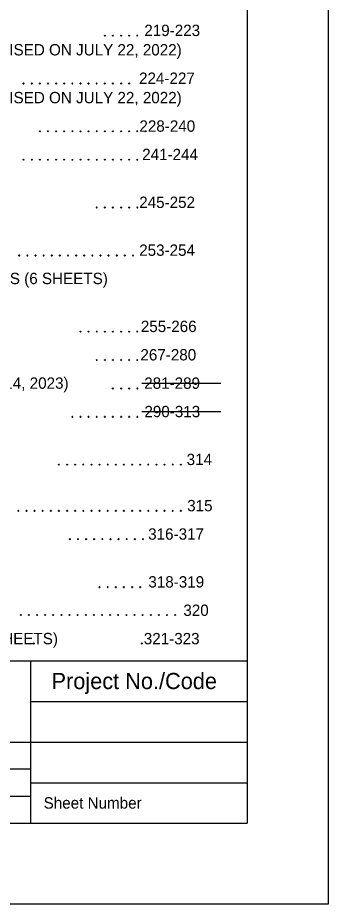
# Model space of a CAD drawing. Extents: x 0 to 1.42, y 0 to 0.92.
# Drawn here: x 1.2574 to 1.4167, y 0 to 0.4557 of the extents above; entities that cross this region are included whole.
import ezdxf

# ---------------------------------------------------------------- set-up
doc = ezdxf.new("R2010")
doc.units = 0
for name, color, linetype in [('DRAFT_Text-Notes', 7, 'Continuous'), ('DRAFT_Text-Titles', 7, 'Continuous'), ('SHEET_Lines', 7, 'Continuous'), ('SHEET_Plot Boundary', 7, 'Continuous'), ('SHEET_Text-Border Info', 7, 'Continuous'), ('SHEET_Text-Titles', 7, 'Continuous')]:
    doc.layers.add(name, color=color, linetype=linetype)

msp = doc.modelspace()

# ---------------------------------------------------------------- linework, layer by layer
at = {"layer": 'DRAFT_Text-Notes'}
for centre in [(1.30206, 0.44647), (1.30622, 0.44647), (1.31039, 0.44647), (1.31456, 0.44647), (1.31872, 0.44647), (1.26039, 0.42188), (1.26456, 0.42188), (1.26872, 0.42188), (1.27289, 0.42188), (1.27706, 0.42188), (1.28122, 0.42188), (1.28539, 0.42188), (1.28956, 0.42188), (1.29372, 0.42188), (1.29789, 0.42188), (1.30206, 0.42188), (1.30622, 0.42188), (1.31039, 0.42188), (1.31456, 0.42188), (1.26872, 0.39729), (1.27289, 0.39729), (1.27706, 0.39729), (1.28122, 0.39729), (1.28539, 0.39729), (1.28956, 0.39729), (1.29372, 0.39729), (1.29789, 0.39729), (1.30206, 0.39729), (1.30622, 0.39729), (1.31039, 0.39729), (1.31456, 0.39729), (1.31872, 0.39729), (1.32289, 0.39729), (1.26039, 0.3827), (1.26456, 0.3827), (1.26872, 0.3827), (1.27289, 0.3827), (1.27706, 0.3827), (1.28122, 0.3827), (1.28539, 0.3827), (1.28956, 0.3827), (1.29372, 0.3827), (1.29789, 0.3827), (1.30206, 0.3827), (1.30622, 0.3827), (1.31039, 0.3827), (1.31456, 0.3827), (1.31872, 0.3827), (1.29789, 0.3581), (1.30206, 0.3581), (1.30622, 0.3581), (1.31039, 0.3581), (1.31456, 0.3581), (1.31872, 0.3581), (1.25816, 0.33351), (1.26232, 0.33351), (1.26649, 0.33351), (1.27066, 0.33351), (1.27482, 0.33351), (1.27899, 0.33351), (1.28316, 0.33351), (1.28732, 0.33351), (1.29149, 0.33351), (1.29566, 0.33351), (1.29982, 0.33351), (1.30399, 0.33351), (1.30816, 0.33351), (1.31232, 0.33351), (1.31649, 0.33351), (1.28956, 0.29433), (1.29372, 0.29433), (1.29789, 0.29433), (1.30206, 0.29433), (1.30622, 0.29433), (1.31039, 0.29433), (1.31456, 0.29433), (1.31872, 0.29433), (1.29789, 0.27974), (1.30206, 0.27974), (1.30622, 0.27974), (1.31039, 0.27974), (1.31456, 0.27974), (1.31872, 0.27974), (1.30622, 0.26514), (1.31039, 0.26514), (1.31456, 0.26514), (1.31872, 0.26514), (1.28539, 0.25055), (1.28956, 0.25055), (1.29372, 0.25055), (1.29789, 0.25055), (1.30206, 0.25055), (1.30622, 0.25055), (1.31039, 0.25055), (1.31456, 0.25055), (1.31872, 0.25055), (1.27852, 0.22596), (1.28269, 0.22596), (1.28686, 0.22596), (1.29102, 0.22596), (1.29519, 0.22596), (1.29936, 0.22596), (1.30352, 0.22596), (1.30769, 0.22596), (1.31186, 0.22596), (1.31602, 0.22596), (1.32019, 0.22596), (1.32436, 0.22596), (1.32852, 0.22596), (1.33269, 0.22596), (1.33686, 0.22596), (1.34102, 0.22596), (1.25769, 0.2022), (1.26186, 0.2022), (1.26602, 0.2022), (1.27019, 0.2022), (1.27436, 0.2022), (1.27852, 0.2022), (1.28269, 0.2022), (1.28686, 0.2022), (1.29102, 0.2022), (1.29519, 0.2022), (1.29936, 0.2022), (1.30352, 0.2022), (1.30769, 0.2022), (1.31186, 0.2022), (1.31602, 0.2022), (1.32019, 0.2022), (1.32436, 0.2022), (1.32852, 0.2022), (1.33269, 0.2022), (1.33686, 0.2022), (1.34102, 0.2022), (1.28412, 0.1876), (1.28828, 0.1876), (1.29245, 0.1876), (1.29662, 0.1876), (1.30078, 0.1876), (1.30495, 0.1876), (1.30912, 0.1876), (1.31328, 0.1876), (1.31745, 0.1876), (1.32162, 0.1876), (1.29936, 0.16301), (1.30352, 0.16301), (1.30769, 0.16301), (1.31186, 0.16301), (1.31602, 0.16301), (1.32019, 0.16301), (1.25895, 0.14866), (1.26311, 0.14866), (1.26728, 0.14866), (1.27145, 0.14866), (1.27561, 0.14866), (1.27978, 0.14866), (1.28395, 0.14866), (1.28811, 0.14866), (1.29228, 0.14866), (1.29645, 0.14866), (1.30061, 0.14866), (1.30478, 0.14866), (1.30895, 0.14866), (1.31311, 0.14866), (1.31728, 0.14866), (1.32145, 0.14866), (1.32561, 0.14866), (1.32978, 0.14866), (1.33395, 0.14866), (1.33811, 0.14866), (1.26568, 0.13407), (1.321, 0.13407)]:
    msp.add_circle(centre, 0.000208, dxfattribs=at)
for centre, start, end in [((1.30206, 0.44647), 0, 180), ((1.30622, 0.44647), 0, 180), ((1.31039, 0.44647), 0, 180), ((1.31456, 0.44647), 0, 180), ((1.31872, 0.44647), 0, 180), ((1.30206, 0.44647), 180, 0), ((1.30622, 0.44647), 180, 0), ((1.31039, 0.44647), 180, 0), ((1.31456, 0.44647), 180, 0), ((1.31872, 0.44647), 180, 0), ((1.26039, 0.42188), 0, 180), ((1.26039, 0.42188), 180, 0), ((1.26456, 0.42188), 0, 180), ((1.26456, 0.42188), 180, 0), ((1.26872, 0.42188), 0, 180), ((1.26872, 0.42188), 180, 0), ((1.27289, 0.42188), 0, 180), ((1.27289, 0.42188), 180, 0), ((1.27706, 0.42188), 0, 180), ((1.27706, 0.42188), 180, 0), ((1.28122, 0.42188), 0, 180), ((1.28122, 0.42188), 180, 0), ((1.28539, 0.42188), 0, 180), ((1.28539, 0.42188), 180, 0), ((1.28956, 0.42188), 0, 180), ((1.28956, 0.42188), 180, 0), ((1.29372, 0.42188), 0, 180), ((1.29372, 0.42188), 180, 0), ((1.29789, 0.42188), 0, 180), ((1.29789, 0.42188), 180, 0), ((1.30206, 0.42188), 0, 180), ((1.30206, 0.42188), 180, 0), ((1.30622, 0.42188), 0, 180), ((1.30622, 0.42188), 180, 0), ((1.31039, 0.42188), 0, 180), ((1.31039, 0.42188), 180, 0), ((1.31456, 0.42188), 0, 180), ((1.31456, 0.42188), 180, 0), ((1.26872, 0.39729), 0, 180), ((1.26872, 0.39729), 180, 0), ((1.27289, 0.39729), 0, 180), ((1.27289, 0.39729), 180, 0), ((1.27706, 0.39729), 0, 180), ((1.27706, 0.39729), 180, 0), ((1.28122, 0.39729), 0, 180), ((1.28122, 0.39729), 180, 0), ((1.28539, 0.39729), 0, 180), ((1.28539, 0.39729), 180, 0), ((1.28956, 0.39729), 0, 180), ((1.28956, 0.39729), 180, 0), ((1.29372, 0.39729), 0, 180), ((1.29372, 0.39729), 180, 0), ((1.29789, 0.39729), 0, 180), ((1.29789, 0.39729), 180, 0), ((1.30206, 0.39729), 0, 180), ((1.30206, 0.39729), 180, 0), ((1.30622, 0.39729), 0, 180), ((1.30622, 0.39729), 180, 0), ((1.31039, 0.39729), 0, 180), ((1.31039, 0.39729), 180, 0), ((1.31456, 0.39729), 0, 180), ((1.31456, 0.39729), 180, 0), ((1.31872, 0.39729), 0, 180), ((1.31872, 0.39729), 180, 0), ((1.32289, 0.39729), 0, 180), ((1.32289, 0.39729), 180, 0), ((1.26039, 0.3827), 0, 180), ((1.26456, 0.3827), 0, 180), ((1.26872, 0.3827), 0, 180), ((1.27289, 0.3827), 0, 180), ((1.27706, 0.3827), 0, 180), ((1.28122, 0.3827), 0, 180), ((1.28539, 0.3827), 0, 180), ((1.28956, 0.3827), 0, 180), ((1.29372, 0.3827), 0, 180), ((1.29789, 0.3827), 0, 180), ((1.30206, 0.3827), 0, 180), ((1.30622, 0.3827), 0, 180), ((1.31039, 0.3827), 0, 180), ((1.31456, 0.3827), 0, 180), ((1.31872, 0.3827), 0, 180), ((1.26039, 0.3827), 180, 0), ((1.26456, 0.3827), 180, 0), ((1.26872, 0.3827), 180, 0), ((1.27289, 0.3827), 180, 0), ((1.27706, 0.3827), 180, 0), ((1.28122, 0.3827), 180, 0), ((1.28539, 0.3827), 180, 0), ((1.28956, 0.3827), 180, 0), ((1.29372, 0.3827), 180, 0), ((1.29789, 0.3827), 180, 0), ((1.30206, 0.3827), 180, 0), ((1.30622, 0.3827), 180, 0), ((1.31039, 0.3827), 180, 0), ((1.31456, 0.3827), 180, 0), ((1.31872, 0.3827), 180, 0), ((1.29789, 0.3581), 0, 180), ((1.29789, 0.3581), 180, 0), ((1.30206, 0.3581), 0, 180), ((1.30206, 0.3581), 180, 0), ((1.30622, 0.3581), 0, 180), ((1.30622, 0.3581), 180, 0), ((1.31039, 0.3581), 0, 180), ((1.31039, 0.3581), 180, 0), ((1.31456, 0.3581), 0, 180), ((1.31456, 0.3581), 180, 0), ((1.31872, 0.3581), 0, 180), ((1.31872, 0.3581), 180, 0), ((1.25816, 0.33351), 0, 180), ((1.25816, 0.33351), 180, 0), ((1.26232, 0.33351), 0, 180), ((1.26232, 0.33351), 180, 0), ((1.26649, 0.33351), 0, 180), ((1.26649, 0.33351), 180, 0), ((1.27066, 0.33351), 0, 180), ((1.27066, 0.33351), 180, 0), ((1.27482, 0.33351), 0, 180), ((1.27482, 0.33351), 180, 0), ((1.27899, 0.33351), 0, 180), ((1.27899, 0.33351), 180, 0), ((1.28316, 0.33351), 0, 180), ((1.28316, 0.33351), 180, 0), ((1.28732, 0.33351), 0, 180), ((1.28732, 0.33351), 180, 0), ((1.29149, 0.33351), 0, 180), ((1.29149, 0.33351), 180, 0), ((1.29566, 0.33351), 0, 180), ((1.29566, 0.33351), 180, 0), ((1.29982, 0.33351), 0, 180), ((1.29982, 0.33351), 180, 0), ((1.30399, 0.33351), 0, 180), ((1.30399, 0.33351), 180, 0), ((1.30816, 0.33351), 0, 180), ((1.30816, 0.33351), 180, 0), ((1.31232, 0.33351), 0, 180), ((1.31232, 0.33351), 180, 0), ((1.31649, 0.33351), 0, 180), ((1.31649, 0.33351), 180, 0), ((1.28956, 0.29433), 0, 180), ((1.28956, 0.29433), 180, 0), ((1.29372, 0.29433), 0, 180), ((1.29372, 0.29433), 180, 0), ((1.29789, 0.29433), 0, 180), ((1.29789, 0.29433), 180, 0), ((1.30206, 0.29433), 0, 180), ((1.30206, 0.29433), 180, 0), ((1.30622, 0.29433), 0, 180), ((1.30622, 0.29433), 180, 0), ((1.31039, 0.29433), 0, 180), ((1.31039, 0.29433), 180, 0), ((1.31456, 0.29433), 0, 180), ((1.31456, 0.29433), 180, 0), ((1.31872, 0.29433), 0, 180), ((1.31872, 0.29433), 180, 0), ((1.29789, 0.27974), 0, 180), ((1.29789, 0.27974), 180, 0), ((1.30206, 0.27974), 0, 180), ((1.30206, 0.27974), 180, 0), ((1.30622, 0.27974), 0, 180), ((1.30622, 0.27974), 180, 0), ((1.31039, 0.27974), 0, 180), ((1.31039, 0.27974), 180, 0), ((1.31456, 0.27974), 0, 180), ((1.31456, 0.27974), 180, 0), ((1.31872, 0.27974), 0, 180), ((1.31872, 0.27974), 180, 0), ((1.30622, 0.26514), 0, 180), ((1.30622, 0.26514), 180, 0), ((1.31039, 0.26514), 0, 180), ((1.31039, 0.26514), 180, 0), ((1.31456, 0.26514), 0, 180), ((1.31456, 0.26514), 180, 0), ((1.31872, 0.26514), 0, 180), ((1.31872, 0.26514), 180, 0), ((1.28539, 0.25055), 0, 180), ((1.28956, 0.25055), 0, 180), ((1.29372, 0.25055), 0, 180), ((1.29789, 0.25055), 0, 180), ((1.30206, 0.25055), 0, 180), ((1.30622, 0.25055), 0, 180), ((1.31039, 0.25055), 0, 180), ((1.31456, 0.25055), 0, 180), ((1.31872, 0.25055), 0, 180), ((1.28539, 0.25055), 180, 0), ((1.28956, 0.25055), 180, 0), ((1.29372, 0.25055), 180, 0), ((1.29789, 0.25055), 180, 0), ((1.30206, 0.25055), 180, 0), ((1.30622, 0.25055), 180, 0), ((1.31039, 0.25055), 180, 0), ((1.31456, 0.25055), 180, 0), ((1.31872, 0.25055), 180, 0), ((1.27852, 0.22596), 0, 180), ((1.27852, 0.22596), 180, 0), ((1.28269, 0.22596), 0, 180), ((1.28269, 0.22596), 180, 0), ((1.28686, 0.22596), 0, 180), ((1.28686, 0.22596), 180, 0), ((1.29102, 0.22596), 0, 180), ((1.29102, 0.22596), 180, 0), ((1.29519, 0.22596), 0, 180), ((1.29519, 0.22596), 180, 0), ((1.29936, 0.22596), 0, 180), ((1.29936, 0.22596), 180, 0), ((1.30352, 0.22596), 0, 180), ((1.30352, 0.22596), 180, 0), ((1.30769, 0.22596), 0, 180), ((1.30769, 0.22596), 180, 0), ((1.31186, 0.22596), 0, 180), ((1.31186, 0.22596), 180, 0), ((1.31602, 0.22596), 0, 180), ((1.31602, 0.22596), 180, 0), ((1.32019, 0.22596), 0, 180), ((1.32019, 0.22596), 180, 0), ((1.32436, 0.22596), 0, 180), ((1.32436, 0.22596), 180, 0), ((1.32852, 0.22596), 0, 180), ((1.32852, 0.22596), 180, 0), ((1.33269, 0.22596), 0, 180), ((1.33269, 0.22596), 180, 0), ((1.33686, 0.22596), 0, 180), ((1.33686, 0.22596), 180, 0), ((1.34102, 0.22596), 0, 180), ((1.34102, 0.22596), 180, 0), ((1.25769, 0.2022), 0, 180), ((1.25769, 0.2022), 180, 0), ((1.26186, 0.2022), 0, 180), ((1.26186, 0.2022), 180, 0), ((1.26602, 0.2022), 0, 180), ((1.26602, 0.2022), 180, 0), ((1.27019, 0.2022), 0, 180), ((1.27019, 0.2022), 180, 0), ((1.27436, 0.2022), 0, 180), ((1.27436, 0.2022), 180, 0), ((1.27852, 0.2022), 0, 180), ((1.27852, 0.2022), 180, 0), ((1.28269, 0.2022), 0, 180), ((1.28269, 0.2022), 180, 0), ((1.28686, 0.2022), 0, 180), ((1.28686, 0.2022), 180, 0), ((1.29102, 0.2022), 0, 180), ((1.29102, 0.2022), 180, 0), ((1.29519, 0.2022), 0, 180), ((1.29519, 0.2022), 180, 0), ((1.29936, 0.2022), 0, 180), ((1.29936, 0.2022), 180, 0), ((1.30352, 0.2022), 0, 180), ((1.30352, 0.2022), 180, 0), ((1.30769, 0.2022), 0, 180), ((1.30769, 0.2022), 180, 0), ((1.31186, 0.2022), 0, 180), ((1.31186, 0.2022), 180, 0), ((1.31602, 0.2022), 0, 180), ((1.31602, 0.2022), 180, 0), ((1.32019, 0.2022), 0, 180), ((1.32019, 0.2022), 180, 0), ((1.32436, 0.2022), 0, 180), ((1.32436, 0.2022), 180, 0), ((1.32852, 0.2022), 0, 180), ((1.32852, 0.2022), 180, 0), ((1.33269, 0.2022), 0, 180), ((1.33269, 0.2022), 180, 0), ((1.33686, 0.2022), 0, 180), ((1.33686, 0.2022), 180, 0), ((1.34102, 0.2022), 0, 180), ((1.34102, 0.2022), 180, 0), ((1.28412, 0.1876), 0, 180), ((1.28412, 0.1876), 180, 0), ((1.28828, 0.1876), 0, 180), ((1.28828, 0.1876), 180, 0), ((1.29245, 0.1876), 0, 180), ((1.29245, 0.1876), 180, 0), ((1.29662, 0.1876), 0, 180), ((1.29662, 0.1876), 180, 0), ((1.30078, 0.1876), 0, 180), ((1.30078, 0.1876), 180, 0), ((1.30495, 0.1876), 0, 180), ((1.30495, 0.1876), 180, 0), ((1.30912, 0.1876), 0, 180), ((1.30912, 0.1876), 180, 0), ((1.31328, 0.1876), 0, 180), ((1.31328, 0.1876), 180, 0), ((1.31745, 0.1876), 0, 180), ((1.31745, 0.1876), 180, 0), ((1.32162, 0.1876), 0, 180), ((1.32162, 0.1876), 180, 0), ((1.29936, 0.16301), 0, 180), ((1.29936, 0.16301), 180, 0), ((1.30352, 0.16301), 0, 180), ((1.30352, 0.16301), 180, 0), ((1.30769, 0.16301), 0, 180), ((1.30769, 0.16301), 180, 0), ((1.31186, 0.16301), 0, 180), ((1.31186, 0.16301), 180, 0), ((1.31602, 0.16301), 0, 180), ((1.31602, 0.16301), 180, 0), ((1.32019, 0.16301), 0, 180), ((1.32019, 0.16301), 180, 0), ((1.25895, 0.14866), 0, 180), ((1.25895, 0.14866), 180, 0), ((1.26311, 0.14866), 0, 180), ((1.26311, 0.14866), 180, 0), ((1.26728, 0.14866), 0, 180), ((1.26728, 0.14866), 180, 0), ((1.27145, 0.14866), 0, 180), ((1.27145, 0.14866), 180, 0), ((1.27561, 0.14866), 0, 180), ((1.27561, 0.14866), 180, 0), ((1.27978, 0.14866), 0, 180), ((1.27978, 0.14866), 180, 0), ((1.28395, 0.14866), 0, 180), ((1.28395, 0.14866), 180, 0), ((1.28811, 0.14866), 0, 180), ((1.28811, 0.14866), 180, 0), ((1.29228, 0.14866), 0, 180), ((1.29228, 0.14866), 180, 0), ((1.29645, 0.14866), 0, 180), ((1.29645, 0.14866), 180, 0), ((1.30061, 0.14866), 0, 180), ((1.30061, 0.14866), 180, 0), ((1.30478, 0.14866), 0, 180), ((1.30478, 0.14866), 180, 0), ((1.30895, 0.14866), 0, 180), ((1.30895, 0.14866), 180, 0), ((1.31311, 0.14866), 0, 180), ((1.31311, 0.14866), 180, 0), ((1.31728, 0.14866), 0, 180), ((1.31728, 0.14866), 180, 0), ((1.32145, 0.14866), 0, 180), ((1.32145, 0.14866), 180, 0), ((1.32561, 0.14866), 0, 180), ((1.32561, 0.14866), 180, 0), ((1.32978, 0.14866), 0, 180), ((1.32978, 0.14866), 180, 0), ((1.33395, 0.14866), 0, 180), ((1.33395, 0.14866), 180, 0), ((1.33811, 0.14866), 0, 180), ((1.33811, 0.14866), 180, 0), ((1.26568, 0.13407), 0, 180), ((1.26568, 0.13407), 180, 0), ((1.321, 0.13407), 0, 180), ((1.321, 0.13407), 180, 0)]:
    msp.add_arc(centre, 0.000208, start, end, dxfattribs=at)
at = {"layer": 'DRAFT_Text-Titles'}
for p, q in [((1.32109, 0.26781), (1.36153, 0.26781)), ((1.32109, 0.25321), (1.36153, 0.25321))]:
    msp.add_line(p, q, dxfattribs=at)
at = {"layer": 'SHEET_Lines'}
for p, q in [((1.26389, 0.125), (1.26389, 0.04167)), ((1.375, 0.125), (1.375, 0.04167)), ((1.26389, 0.10417), (1.375, 0.10417)), ((0.90278, 0.08333), (1.375, 0.08333)), ((1.26389, 0.06944), (1.18056, 0.06944)), ((1.26389, 0.0625), (1.375, 0.0625)), ((1.01389, 0.05556), (1.26389, 0.05556)), ((0.08333, 0.04167), (1.375, 0.04167))]:
    msp.add_line(p, q, dxfattribs=at)
msp.add_lwpolyline([(0.08333, 0.875), (1.375, 0.875), (1.375, 0.125), (0.08333, 0.125)], close=True, dxfattribs=at)
at = {"layer": 'SHEET_Plot Boundary'}
msp.add_lwpolyline([(0, 0.91667), (1.41667, 0.91667), (1.41667, 0), (0, 0)], close=True, dxfattribs=at)

# ---------------------------------------------------------------- texts
at = {"layer": 'DRAFT_Text-Notes'}
for s, height, p in [('219-223', 0.005833, (1.32232, 0.44626)), ('224-227', 0.005833, (1.3196, 0.42167)), ('228-240', 0.005833, (1.31979, 0.39708)), ('241-244', 0.005833, (1.32122, 0.38249)), ('245-252', 0.005833, (1.3197, 0.3579)), ('253-254', 0.005833, (1.31969, 0.3333)), ('PEDESTRIAN PUSH BUTTON POST ASSEMBLY DETAILS (6 SHEETS)', 0.0058333, (1.0483, 0.31875)), ('255-266', 0.005833, (1.32052, 0.29412)), ('267-280', 0.005833, (1.3203, 0.27953)), ('281-289', 0.005833, (1.32227, 0.26494)), ('290-313', 0.005833, (1.32236, 0.25034)), ('314', 0.005833, (1.34404, 0.22575)), ('315', 0.005833, (1.34431, 0.20199)), ('316-317', 0.005833, (1.32429, 0.18739)), ('318-319', 0.005833, (1.32438, 0.1628)), ('320', 0.005833, (1.34233, 0.14821)), ('ROLLING ROADBLOCKS FOR TRAFFIC CONTROL (3 SHEETS)', 0.0058333, (1.0483, 0.13365)), ('321-323', 0.005833, (1.32204, 0.13362))]:
    msp.add_text(s, height=height, dxfattribs=at).set_placement(p)
at = {"layer": 'DRAFT_Text-Titles'}
for s, p in [('(REVISED ON JULY 22, 2022)', (1.23442, 0.4363)), ('(REVISED ON JULY 22, 2022)', (1.23442, 0.41171)), ('(REV. APRIL 14, 2023)', (1.20283, 0.26497))]:
    msp.add_text(s, height=0.0058333, dxfattribs=at).set_placement(p)
at = {"layer": 'SHEET_Text-Border Info'}
msp.add_text('Sheet Number', height=0.0058333, dxfattribs=at).set_placement((1.27066, 0.04917))
at = {"layer": 'SHEET_Text-Titles'}
msp.add_text('Project No./Code', height=0.0083333, dxfattribs=at).set_placement((1.27473, 0.11059))

doc.saveas('drawing.dxf')
